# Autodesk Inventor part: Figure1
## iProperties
Shininess: 77.0
Angle Display Precision: 2
Document Length Units: 11269
Document Angle Units: 11279
Document Time Units: 11290
Document Mass Units: 11283
Document Length Units Precision: 3
Document Angle Units Precision: 2
Created: 2001-12
Part Number: Figure1
Document SubType Name: Modeling
Designer: Renu Muthoo
Density: 1 g/cm^3
Density: 0.0
Volumn: 0.0
Area: 0.0
PropertySet Name: Model Information
Control State: 0
Master: False
Checked Out: False
Author: Renu Muthoo
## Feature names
1. Extrusion1
2. Extrusion3
3. Chamfer3
